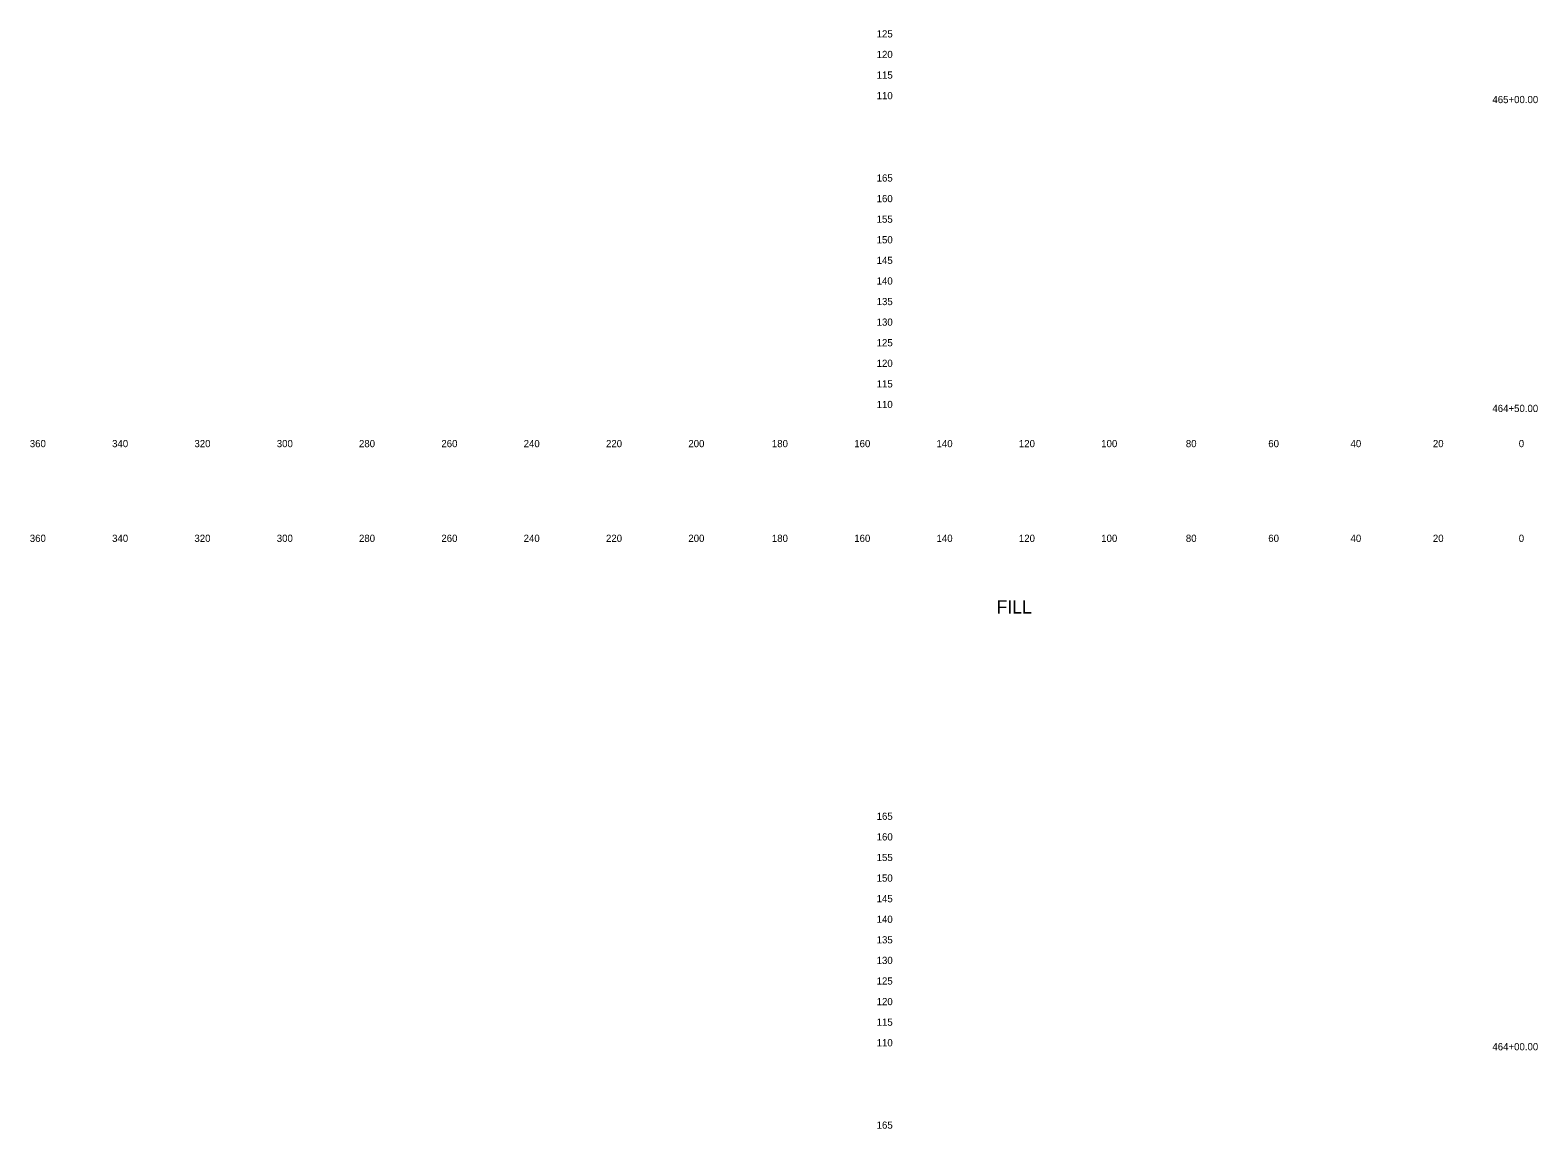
# Model space of a CAD drawing. Extents: x 21281 to 22024, y 6472 to 15198.
# Drawn here: x 21280.5 to 21646.7, y 8379.8 to 8646.6 of the extents above; entities that cross this region are included whole.
import ezdxf

# ---------------------------------------------------------------- set-up
doc = ezdxf.new("R2010")
doc.units = 0
for name, color, linetype in [('XS_SHEET_LABELS_ELEVATION', 7, 'Continuous'), ('XS_SHEET_LABELS_OFFSET', 7, 'Continuous'), ('XS_SHEET_LABELS_STATION', 7, 'Continuous')]:
    doc.layers.add(name, color=color, linetype=linetype)

msp = doc.modelspace()

# ---------------------------------------------------------------- texts
at = {"layer": 'XS_SHEET_LABELS_ELEVATION'}
for s, p in [('  125  ', (21484.84, 8644.84)), ('  120  ', (21484.84, 8639.84)), ('  115  ', (21484.84, 8634.84)), ('  110  ', (21484.84, 8629.84)), ('  165  ', (21484.84, 8609.84)), ('  160  ', (21484.84, 8604.84)), ('  155  ', (21484.84, 8599.84)), ('  150  ', (21484.84, 8594.84)), ('  145  ', (21484.84, 8589.84)), ('  140  ', (21484.84, 8584.84)), ('  135  ', (21484.84, 8579.84)), ('  130  ', (21484.84, 8574.84)), ('  125  ', (21484.84, 8569.84)), ('  120  ', (21484.84, 8564.84)), ('  115  ', (21484.84, 8559.84)), ('  110  ', (21484.84, 8554.84)), ('  165  ', (21484.84, 8454.84)), ('  160  ', (21484.84, 8449.84)), ('  155  ', (21484.84, 8444.84)), ('  150  ', (21484.84, 8439.84)), ('  145  ', (21484.84, 8434.84)), ('  140  ', (21484.84, 8429.84)), ('  135  ', (21484.84, 8424.84)), ('  130  ', (21484.84, 8419.84)), ('  125  ', (21484.84, 8414.84)), ('  120  ', (21484.84, 8409.84)), ('  115  ', (21484.84, 8404.84)), ('  110  ', (21484.84, 8399.84)), ('  165  ', (21484.84, 8379.84))]:
    msp.add_text(s, height=1.75, dxfattribs=at).set_placement(p)
at = {"layer": 'XS_SHEET_LABELS_OFFSET'}
for s, height, p in [('  360  ', 1.75, (21279.14, 8545.34)), ('  340  ', 1.75, (21299.13, 8545.34)), ('  320  ', 1.75, (21319.13, 8545.34)), ('  300  ', 1.75, (21339.13, 8545.34)), ('  280  ', 1.75, (21359.1, 8545.34)), ('  260  ', 1.75, (21379.11, 8545.34)), ('  240  ', 1.75, (21399.1, 8545.34)), ('  220  ', 1.75, (21419.1, 8545.34)), ('  200  ', 1.75, (21439.1, 8545.34)), ('  180  ', 1.75, (21459.39, 8545.34)), ('  160  ', 1.75, (21479.4, 8545.34)), ('  140  ', 1.75, (21499.39, 8545.34)), ('  120  ', 1.75, (21519.39, 8545.34)), ('  100  ', 1.75, (21539.39, 8545.34)), ('  80  ', 1.75, (21559.95, 8545.34)), ('  60  ', 1.75, (21579.97, 8545.34)), ('  40  ', 1.75, (21599.95, 8545.34)), ('  20  ', 1.75, (21619.95, 8545.34)), ('  0  ', 1.75, (21640.81, 8545.34)), ('  0  ', 1.75, (21640.81, 8545.34)), ('  360  ', 1.75, (21279.14, 8522.34)), ('  340  ', 1.75, (21299.13, 8522.34)), ('  320  ', 1.75, (21319.13, 8522.34)), ('  300  ', 1.75, (21339.13, 8522.34)), ('  280  ', 1.75, (21359.1, 8522.34)), ('  260  ', 1.75, (21379.11, 8522.34)), ('  240  ', 1.75, (21399.1, 8522.34)), ('  220  ', 1.75, (21419.1, 8522.34)), ('  200  ', 1.75, (21439.1, 8522.34)), ('  180  ', 1.75, (21459.39, 8522.34)), ('  160  ', 1.75, (21479.4, 8522.34)), ('  140  ', 1.75, (21499.39, 8522.34)), ('  120  ', 1.75, (21519.39, 8522.34)), ('  100  ', 1.75, (21539.39, 8522.34)), ('  80  ', 1.75, (21559.95, 8522.34)), ('  60  ', 1.75, (21579.97, 8522.34)), ('  40  ', 1.75, (21599.95, 8522.34)), ('  20  ', 1.75, (21619.95, 8522.34)), ('  0  ', 1.75, (21640.81, 8522.34)), ('  0  ', 1.75, (21640.81, 8522.34)), ('FILL', 3.222, (21515.23, 8504.95))]:
    msp.add_text(s, height=height, dxfattribs=at).set_placement(p)
at = {"layer": 'XS_SHEET_LABELS_STATION'}
for s, p in [('  465+00.00  ', (21634.41, 8628.89)), ('  464+50.00  ', (21634.41, 8553.89)), ('  464+00.00  ', (21634.41, 8398.89))]:
    msp.add_text(s, height=1.75, dxfattribs=at).set_placement(p)

doc.saveas('drawing.dxf')
